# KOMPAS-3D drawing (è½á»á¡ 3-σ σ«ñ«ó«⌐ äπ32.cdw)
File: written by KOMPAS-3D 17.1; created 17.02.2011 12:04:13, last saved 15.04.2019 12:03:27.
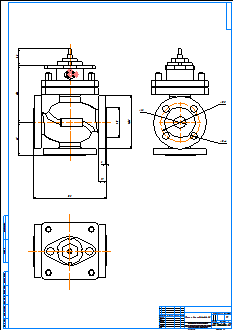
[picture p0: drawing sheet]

Title block, sheet 1: name: Клапан 3-х ходовой Ду32; material: Внимание! Данный продукт является объектом авторского права ООО «Торговый Дом АДЛ». / Запрещается изменение, копирование, распространение / (в том числе путем копирования на другие сайты и ресурсы в Интернете) / или любое иное использование информации и объектов без предварительного / согласия правообладателя (ООО «Торговый Дом АДЛ»).; scale: 1:1; sheets: 1; organisation: ООО "Торговый дом АДЛ"; sheet format: A1; stored path: \\adlc.lan\data\АДЛ_ПКД\3D-модели\ADL production\Клапаны ГРАНРЕГ\Трёхходовой клапан КМ307Ф\KOMPAS 2D\Клапан 3-х ходовой Ду32.cdw

Views: Спереди 1, Проекционный вид 2, Проекционный вид 3
Dimensions and other numbers on the sheet: 85; 146; 43; 185; 3; 19; 78; 135; 100; 18; 32; 1:1; 1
